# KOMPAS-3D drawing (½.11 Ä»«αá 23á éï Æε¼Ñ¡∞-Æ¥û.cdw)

Views: Вид 1, Вид 2, Вид 3, Вид 4
Referenced files: Подвеска ВЧ-заградителя.cdw
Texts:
  Текст на чертеже
  Размерные надписи
  Шероховатость
  Линия-выноска #1
  Линия-выноска #2
  Линия-выноска #3
  Отклонения формы и база
  Заголовок таблицы
  Ячейка таблицы
  Стрелка вида
  Обозначение изменения
  Фигурная скобка
  Номер узла
  Марка координационной оси
  VRCB
  Выносная надпись
  Обозначение узла
  Марка/позиционное обозначение с линией-выноской
  Марка/позиционное обозначение на линии
  Марка/позиционное обозначение без линии-выноски
  ООббыыччнныыйй
  Definition Term
  Definition List
  Address
  Blockquote
  Preformatted
  Courier New
  z-Bottom of Form
  z-Top of Form
  Лит-Масса-Масштаб
  Материал-Предприятие
  Title Specification
  Body Specification ( left align )
  Body Specificaton ( centered )
  Без имени
  SPEC
  Normal
  Txt
  Body Text
  heading 1
  Знак Знак Знак Знак Знак Знак
  Verdana
  Simplex
  TXT
  txt
  MS Sans Serif
  Additional DXF text style 0
  Обычный
  Термин
  Список определений
  Адрес
  Цитаты
  Форматированный
  Z-конец формы
  Z-начало формы
  ТекстШаг1
  Title
  Денис
  header
  heading 2
  AGOpus
  footer
  NormalParagraphStyle
  Body Text 3
  ссылки
  Подпись в квадратике
  табл
  цепи
  Маркировка
  клеммы, контакты
  тексты табл
  Тексты. 3,2
  ЗОНА_привяз
  текст переноса
  ТТееррммиинн
  ССппииссоокк ооппррееддееллеенниийй
  ААддрреесс
  ЦЦииттааттыы
  ФФооррммааттиирроовваанннныыйй
  Z-ккооннеецц ффооррммыы
  Z-ннааччааллоо ффооррммыы
  GOST 2.304 type A
  rustxt
  heading 8
  heading 3
  heading 6
  heading 7
  russ
  Абзац Знак
  heading 4
  heading 5
  heading 9
  HeliosLight
  Pa3
  Pa1
  Три с половиной
  style2
  Шрифт 2.5
  Заголовки
  RUSTXT
  Table Contents
  Table Heading
  ГОСТ_МНЕ
  ESK - Обозначение
  маркировка
  ISOCP
  ROMANS
  SIMPLEX
  Обычный (веб)
  Текст 3,5
  Tahoma
  CNBNDG+TimesNewRoman
  Subtitle
  ISOCPEUR
  FR5
  romans
  Подписи
  Примечание - примечания см. 16/01-ПОС, л.10.
  Схема монтажа ВЧ-заградителя на опору №1.
  Отпайка ВЛ-110 кВ Тюмень - ТТЭЦ-1 3 цепь на ПС Ембаево
  Кран КС-35719-1-02
  CONTINUOUS_RGB_0_0_0_THICK_0.13
  GOST2.303 4_RGB_0_0_0_SC_0.04_THICK_0.13
  CONTINUOUS_RGB_0_0_0_THICK_0.18
  CONTINUOUS_RGB_173_173_173_THICK_0.13
  GOST2.303 4_RGB_173_173_173_SC_0.04_THICK_0.13
  СONTINUOUS_RGB_0_0_0_THICK_0.13
  POLYLINE_STYLE_0.30_RGB_0_0_0
  CONTINUOUS_RGB_0_0_0_THICK_0.3
  GOST2.303 6_RGB_0_0_0_SC_0.04_THICK_0.13
  POLYLINE_STYLE_0.18_RGB_0_0_0
  GOST2.303 6_RGB_0_0_0_SC_0_THICK_0.18
  K5LT_AXLED_RGB_255_128_0_SC_1_THICK_0.18
  CONTINUOUS_RGB_0_0_0_THICK_0.25
  POLYLINE_STYLE_0.21_RGB_0_0_0
  СONTINUOUS_RGB_0_0_0_THICK_0.18
  POLYLINE_STYLE_0.50_RGB_0_0_0
  POLYLINE_STYLE_0.40_RGB_0_0_0
  CONTINUOUS_RGB_0_0_0_THICK_0.6
  Стили документа
  Автомобильный кран КС-35714
  Ромин
  Подвеска ВЧ-заградителя
  на опоре №23а
  Политова
  Разраб.
  Микрюков
  Схема пневматическая соединений
  Перезавод ВЛ на ПС Тюмень. Реконструкция устройств
  РЗ и ПА на обратных концах отходящих ВЛ,
  ВОЛС Тюменского ТПО
  ВЛ 110 кВ Тюмень-
  Тюменская ТЭЦ-1 3 цепь
  Нов.
  ГИП
  Матвеев
Dimensions and other numbers on the sheet: 16/01-ПОС; 7; 3,2_; 3.5; 2.5; 2,5; 1,8; 3,2; 2,5 (контакты, клеммы); 3,2 (надписи); 3,2 (Зоны); 5; 2,5_01; 2,5_3; 3,5_01; 3,5_tabl; 5_заголовок; 2,3_; 3,2_зона не привяз; 3,5; 3.2 маркировка; 3,2 элементы; 3,2 линия; 3,2 таблица; 2,5 грязносинь; 2.5 курсив; 2.5_Э5_надписи; 2.5_Э5_ссылки; 2.5_кабель; 3.2; 2.5 надписи; 3 и 5; 5,0_белый_подчёркнутый; 3.2 фиол; 3.2 (текст); 10500; 4000; 4800; 3000; 6200; 12; 4; 05.14; -091-02-ЭП-; 11; 3; 253-14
